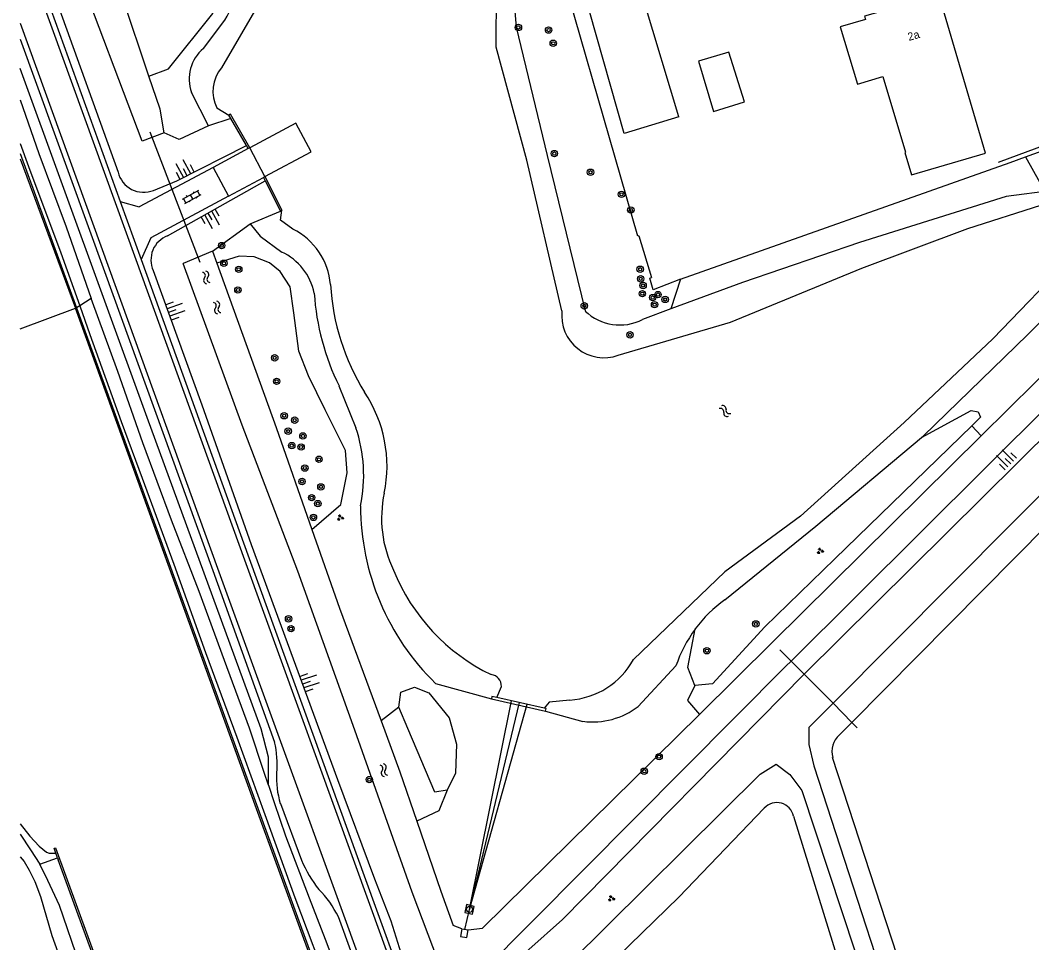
# Model space of a CAD drawing. Extents: x 135999 to 138000, y 396000 to 398501.
# Drawn here: x 136000 to 136126.4, y 396208.2 to 396323.5 of the extents above; entities that cross this region are included whole.
import ezdxf

# ---------------------------------------------------------------- set-up
doc = ezdxf.new("R2010")
doc.units = 0
for name, color, linetype in [('gg-afsc-draadraster', 7, 'Continuous'), ('gg-afsc-erfafscheiding', 7, 'Continuous'), ('gg-afsc-hekwerk', 7, 'Continuous'), ('gg-afsc-muur', 7, 'Continuous'), ('gg-anno-huisnummerreeks BGT', 7, 'Continuous'), ('gg-bbg-bijgebouw', 7, 'Continuous'), ('gg-bbg-gedigitaliseerde bijgebouw', 7, 'Continuous'), ('gg-bbg-hoofdgebouw', 7, 'Continuous'), ('gg-knt-BGT kruinlijn', 7, 'Continuous'), ('gg-knt-bovenkant onderkant talud', 7, 'Continuous'), ('gg-knt-verharding', 7, 'Continuous'), ('gg-knt-verharding nz', 7, 'Continuous'), ('gg-kntw-bovenkant insteek waterloop', 7, 'Continuous'), ('gg-kntw-waterlijn', 7, 'Continuous'), ('gg-kwrk-betonelement', 7, 'Continuous'), ('gg-kwrk-duiker nz buis', 7, 'Continuous'), ('gg-kwrk-keermuur', 7, 'Continuous'), ('gg-kwrk-steiger', 7, 'Continuous'), ('gt-grn-groengrens', 7, 'Continuous'), ('gt-grn-vlakafsluiter', 7, 'Continuous'), ('gt-symb-boom', 7, 'Continuous'), ('gt-symb-groenvak', 7, 'Continuous'), ('gt-symb-klinker verharding', 7, 'Continuous'), ('gt-symb-rioolschacht', 7, 'Continuous'), ('gt-symb-talud symbool', 7, 'Continuous'), ('gt-symb-watersymbool', 7, 'Continuous'), ('gx-grn-maaiveld', 7, 'Continuous')]:
    doc.layers.add(name, color=color, linetype=linetype)

# ---------------------------------------------------------------- blocks, each defined once
blk = doc.blocks.new('gt0-BOOM')
at = {"layer": 'gt-symb-boom'}
for radius in [0.4, 0.2]:
    blk.add_circle((0, 0), radius, dxfattribs=at)
blk = doc.blocks.new('gt0-GRVAK')
at = {"layer": 'gt-symb-groenvak'}
for p, q in [((-0.11, 0.19), (-0.23, 0.24)), ((-0.18, 0.15), (0.09, 0.15)), ((-0.09, 0.21), (-0.16, 0.32)), ((-0.05, 0.21), (-0.05, 0.39)), ((0, 0.21), (0.06, 0.32)), ((0.02, 0.19), (0.13, 0.24)), ((0.26, -0.05), (0.2, 0.06)), ((0.3, -0.05), (0.3, 0.13)), ((0.35, -0.05), (0.41, 0.06)), ((-0.24, -0.23), (-0.36, -0.18)), ((-0.32, -0.26), (-0.05, -0.26)), ((-0.23, -0.21), (-0.29, -0.1)), ((-0.18, -0.2), (-0.18, -0.02)), ((-0.14, -0.21), (-0.07, -0.1)), ((-0.12, -0.23), (0, -0.18)), ((0.24, -0.07), (0.12, -0.02)), ((0.17, -0.11), (0.44, -0.11)), ((0.37, -0.07), (0.49, -0.02))]:
    blk.add_line(p, q, dxfattribs=at)
blk = doc.blocks.new('gt0-TALUD_1')
at = {"layer": 'gt-symb-talud symbool'}
for p, q in [((-1, -1), (-1, 0)), ((-0.5, -2), (-0.5, 0)), ((0, -1), (0, 0)), ((0.5, -2), (0.5, 0)), ((1, -1), (1, 0))]:
    blk.add_line(p, q, dxfattribs=at)
blk = doc.blocks.new('gt0-WA')
at = {"layer": 'gt-symb-watersymbool'}
for centre, start, end in [((-0.32, 0.02), 28.0725, 151.9275), ((0.43, 0.42), 208.0725, 331.9275), ((-0.32, -0.43), 28.0725, 151.9275), ((0.43, -0.03), 208.0725, 331.9275)]:
    blk.add_arc(centre, 0.425, start, end, dxfattribs=at)
blk = doc.blocks.new('gt0-KL1')
at = {"layer": 'gt-symb-klinker verharding'}
for p, q in [((-1.15, 0.3), (1.15, 0.3)), ((-1, -0.3), (-1, 0.3)), ((-0.5, 0.3), (-0.5, 0.45)), ((0, -0.3), (0, 0.3)), ((0.5, 0.3), (0.5, 0.45)), ((1, -0.3), (1, 0.3)), ((-1.15, -0.3), (1.15, -0.3)), ((-0.5, -0.45), (-0.5, -0.3)), ((0.5, -0.45), (0.5, -0.3))]:
    blk.add_line(p, q, dxfattribs=at)
blk = doc.blocks.new('gt0-RS')
at = {"layer": 'gt-symb-rioolschacht'}
blk.add_lwpolyline([(-0.5, -0.5), (0.5, -0.5), (0.5, 0.5), (-0.5, 0.5)], close=True, dxfattribs=at)
blk.add_circle((0, 0), 0.375, dxfattribs=at)

msp = doc.modelspace()

# ---------------------------------------------------------------- linework, layer by layer
at = {"layer": 'gg-afsc-draadraster'}
for points in [[(136125.62, 396306.42), (136139.39, 396311.41), (136159.16, 396318.61)], [(136082.52, 396291.13), (136123.7, 396305.72), (136125.62, 396306.42)]]:
    msp.add_lwpolyline(points, dxfattribs=at)
at = {"layer": 'gg-afsc-erfafscheiding'}
msp.add_line((136077.31, 396296.55), (136078.88, 396291.36), dxfattribs=at)
at = {"layer": 'gg-afsc-hekwerk'}
for p, q in [((136096.32, 396243.39), (136094.91, 396244.81)), ((136097.96, 396241.74), (136096.32, 396243.39)), ((136097.96, 396241.74), (136096.32, 396243.39)), ((136097.96, 396241.74), (136101.56, 396238.11)), ((136097.96, 396241.74), (136101.56, 396238.11)), ((136101.56, 396238.11), (136103.9, 396235.72)), ((136103.9, 396235.72), (136104.56, 396235.04))]:
    msp.add_line(p, q, dxfattribs=at)
msp.add_lwpolyline([(136164.75, 396321.37), (136140.07, 396312.37), (136122.18, 396305.73)], dxfattribs=at)
at = {"layer": 'gg-afsc-muur'}
for p, q in [((136058.88, 396238.66), (136065.64, 396237.12)), ((136065.46, 396237.51), (136059.55, 396238.85))]:
    msp.add_line(p, q, dxfattribs=at)
for points in [[(136059.55, 396238.85), (136058.94, 396238.98), (136058.88, 396238.66)], [(136065.64, 396237.12), (136065.72, 396237.46), (136065.46, 396237.51)]]:
    msp.add_lwpolyline(points, dxfattribs=at)
at = {"layer": 'gg-bbg-bijgebouw'}
for points in [[(136082.31, 396311.42), (136075.46, 396309.35), (136071.18, 396324.49), (136077.76, 396326.53)], [(136088.54, 396319.52), (136084.74, 396318.39), (136086.62, 396312.1), (136090.49, 396313.31), (136088.54, 396319.52)]]:
    msp.add_lwpolyline(points, dxfattribs=at)
at = {"layer": 'gg-bbg-gedigitaliseerde bijgebouw'}
msp.add_line((136082.31, 396311.42), (136078.02, 396325.69), dxfattribs=at)
at = {"layer": 'gg-bbg-hoofdgebouw'}
msp.add_lwpolyline([(136120.61, 396306.9), (136114.88, 396326.48), (136115.66, 396326.71), (136115.6, 396326.91), (136105.5, 396324.01), (136105.62, 396323.62), (136102.46, 396322.67), (136104.61, 396315.52), (136107.77, 396316.48), (136110.62, 396307.01), (136110.53, 396306.98), (136111.37, 396304.19), (136120.61, 396306.9)], dxfattribs=at)
at = {"layer": 'gg-knt-BGT kruinlijn'}
for p, q in [((136000, 396338.48), (136012.22, 396304.51)), ((136018.41, 396296.55), (136030.6, 396303.42))]:
    msp.add_line(p, q, dxfattribs=at)
for points in [[(136097.96, 396241.74), (136142.57, 396285.95), (136173.07, 396316.22)], [(136016.66, 396302.23), (136019.58, 396303.43), (136028.26, 396307.87)], [(136016.63, 396292.22), (136022.7, 396275.44), (136028.87, 396257.96), (136039.65, 396228.6), (136044.28, 396216.18), (136046.32, 396210.91), (136047.56, 396206.9), (136051.38, 396196.06), (136052.81, 396192.4), (136054.26, 396188.42), (136055.79, 396184.75), (136058.58, 396177.23), (136060.05, 396173.56), (136062.86, 396166.3), (136065.69, 396158.09), (136067.16, 396153.6), (136070.41, 396145.41), (136071.87, 396141.49), (136073.34, 396137.14), (136076.44, 396128.34), (136078.07, 396123.94), (136079.51, 396119.81), (136081.08, 396115.98)], [(136099.46, 396076.07), (136105, 396078.09), (136102.59, 396086), (136099.23, 396095.19), (136095.44, 396104.87), (136091.87, 396114.62), (136076.98, 396156.28), (136065.07, 396188.86), (136062.02, 396197.29), (136059.35, 396203.57), (136067.77, 396211.09), (136097.96, 396241.74)]]:
    msp.add_lwpolyline(points, dxfattribs=at)
for centre, radius, start, end in [((136015.43, 396305.31), 3.31, 193.9968, 291.6714), ((136019.53, 396293.56), 3.2, 110.4769, 204.7988)]:
    msp.add_arc(centre, radius, start, end, dxfattribs=at)
at = {"layer": 'gg-knt-bovenkant onderkant talud'}
msp.add_line((136024.02, 396294.62), (136028.75, 396298.07), dxfattribs=at)
msp.add_lwpolyline([(136023.52, 396310.3), (136019.86, 396308.62), (136017.99, 396309.42)], dxfattribs=at)
at = {"layer": 'gg-knt-verharding'}
for p, q in [((136000, 396335.42), (136012.5, 396300.86)), ((136024.09, 396305.09), (136014.85, 396300.19)), ((136026.01, 396301.52), (136016.33, 396296.3)), ((136012.5, 396300.86), (136014.85, 396300.19)), ((136012.5, 396300.86), (136015.12, 396293.6)), ((136016.33, 396296.3), (136015.12, 396293.6)), ((136032.51, 396225.59), (136035.15, 396218.49))]:
    msp.add_line(p, q, dxfattribs=at)
for points in [[(136000, 396321.15), (136010.54, 396292.08), (136024.05, 396254.73), (136031.77, 396233.27)], [(136015.12, 396293.6), (136028.61, 396256.23), (136044.37, 396212.74), (136063.6, 396159.74), (136083.9, 396103.87), (136103.1, 396050.64)], [(136105.83, 396025.3), (136105.27, 396030.32), (136079.38, 396102.18), (136059.08, 396158.12), (136039.75, 396211.42)]]:
    msp.add_lwpolyline(points, dxfattribs=at)
for centre, radius, start, end in [((136020.78, 396230.56), 11.33, 354.1582, 13.8613), ((136042.92, 396228.78), 10.9, 176.6973, 197.0355), ((136047.85, 396223.57), 13.67, 201.8032, 219.6565), ((136027.63, 396205.39), 13.54, 26.4368, 44.2996)]:
    msp.add_arc(centre, radius, start, end, dxfattribs=at)
at = {"layer": 'gg-knt-verharding nz'}
for points in [[(136000, 396333.52), (136014.43, 396293.61), (136028.03, 396256.03), (136043.81, 396212.53), (136062.99, 396159.62), (136083.31, 396103.68), (136102.82, 396049.91), (136105.57, 396041.82), (136108.64, 396032.55), (136110.53, 396027.02)], [(136000, 396323.15), (136011.1, 396292.41), (136024.65, 396254.99), (136040.38, 396211.67), (136059.7, 396158.37), (136079.98, 396102.51), (136107.33, 396025.85)]]:
    msp.add_lwpolyline(points, dxfattribs=at)
at = {"layer": 'gg-kntw-bovenkant insteek waterloop'}
for p, q in [((136016.08, 396316.53), (136011.83, 396329.17)), ((136022.89, 396319.96), (136025.56, 396323.51)), ((136023.52, 396310.3), (136021.4, 396314.49)), ((136026.33, 396311.21), (136023.52, 396310.3)), ((136028.75, 396298.07), (136032.51, 396299.66)), ((136024.02, 396294.62), (136020.35, 396293.09)), ((136024.02, 396294.62), (136024.56, 396293.14)), ((136081.3, 396287.41), (136077.77, 396286.1)), ((136039.83, 396277.79), (136041.95, 396272.56)), ((136077.23, 396237.72), (136081.93, 396242.78)), ((136051.89, 396240.6), (136058.88, 396238.66)), ((136084.86, 396236.72), (136057.77, 396210)), ((136065.64, 396237.12), (136070.32, 396235.85)), ((136055.17, 396209.91), (136054.1, 396210.35)), ((136055.96, 396209.78), (136057.77, 396210))]:
    msp.add_line(p, q, dxfattribs=at)
for points in [[(136101.56, 396238.11), (136146.21, 396283.02), (136182.31, 396318.53), (136148.6, 396349.34)], [(136061.06, 396334.58), (136061.41, 396329.14), (136061.96, 396322.65), (136065.84, 396306.58), (136070.58, 396287.16)], [(136017.99, 396309.42), (136015.23, 396308.4), (136006.93, 396330.37)], [(136017.99, 396309.42), (136017.48, 396312.38), (136016.08, 396316.53)], [(136169.95, 396316.56), (136161.19, 396307.92), (136096.32, 396243.39)], [(136158.3, 396309.14), (136156.82, 396307.63), (136136.93, 396288.21), (136120.09, 396271.55)], [(136129, 396302.22), (136123.21, 396301.49), (136104.89, 396295.72), (136090.26, 396290.74), (136081.3, 396287.41)], [(136028.75, 396298.07), (136030, 396296.52), (136032.68, 396294.53)], [(136024.56, 396293.14), (136031.98, 396272.6), (136036.45, 396259.84)], [(136112.62, 396271.35), (136112.87, 396271.56), (136125.85, 396284.17), (136135.21, 396293.4)], [(136120.09, 396271.55), (136094, 396245.74), (136084.86, 396236.72)], [(136088.05, 396251.06), (136099.42, 396260.26), (136112.62, 396271.35)], [(136036.45, 396259.84), (136039.89, 396250), (136045.1, 396235.92)], [(136057.74, 396204.54), (136095.67, 396242.74), (136096.32, 396243.39)], [(136101.56, 396238.11), (136098.54, 396235.1), (136098.56, 396232.96), (136099.16, 396230.29), (136112.79, 396188.38), (136115.59, 396186.31), (136116.55, 396181.41), (136115.85, 396179.95), (136116.19, 396177.8), (136128.35, 396140.26), (136129.09, 396138.62)], [(136045.1, 396235.92), (136047.45, 396229.56), (136049.56, 396223.38)], [(136066.94, 396202.94), (136068.69, 396205.65), (136092.44, 396229.25), (136094.46, 396230.51), (136096.16, 396229.22), (136097.65, 396227.2), (136110.94, 396187.01), (136110.25, 396184.13), (136111.21, 396181.02), (136113.38, 396179.03), (136114.56, 396176.49), (136127.07, 396137.57), (136128.08, 396134.08)], [(136049.56, 396223.38), (136052.56, 396214.64), (136054.1, 396210.35)]]:
    msp.add_lwpolyline(points, dxfattribs=at)
for centre, radius, start, end in [((136017.07, 396328.8), 10, 328.0603, 19.6418), ((136026, 396316.18), 4.9, 129.421, 200.2034), ((136029.64, 396287.97), 7.23, 11.2888, 65.1731), ((136067.5, 396291.39), 30.83, 183.7293, 206.1772), ((136074.92, 396291.68), 6.27, 226.1784, 297.0462), ((136024.32, 396266.62), 18.6, 348.1374, 18.6065), ((136073.63, 396262.85), 31.11, 180.0953, 225.6687), ((136097.98, 396237.34), 16.94, 125.8733, 143.5668), ((136098, 396237.3), 16.98, 143.5211, 161.1749), ((136071.54, 396245.05), 9.27, 262.4398, 307.8275)]:
    msp.add_arc(centre, radius, start, end, dxfattribs=at)
at = {"layer": 'gg-kntw-waterlijn'}
for p, q in [((136029.85, 396325.66), (136025.15, 396317.56)), ((136024.58, 396312.55), (136026.07, 396311.66)), ((136059.55, 396238.85), (136060.12, 396240.2)), ((136102.33, 396234.14), (136103.9, 396235.72))]:
    msp.add_line(p, q, dxfattribs=at)
for points in [[(136067.69, 396287.18), (136063.31, 396306.01), (136059.47, 396320.13), (136059.5, 396327.2)], [(136103.9, 396235.72), (136144.68, 396276.92), (136184.94, 396317.17)], [(136034.06, 396297.38), (136032.54, 396298.51), (136032.68, 396299.76)], [(136074.72, 396281.64), (136088.75, 396285.76), (136105.15, 396292.53), (136118.42, 396297.48), (136127.55, 396300.39)], [(136131.73, 396294.25), (136121.55, 396283.68), (136110.46, 396273.23), (136097.51, 396261.5), (136088.04, 396254.54), (136076.63, 396243.58)], [(136068.69, 396238.52), (136066.1, 396238.27), (136065.46, 396237.51)], [(136130.86, 396142.59), (136121.77, 396169.2), (136118.71, 396180.62), (136118.51, 396183.1), (136117.85, 396186.47), (136114.96, 396190.11), (136101.51, 396231.33)], [(136071.57, 396203.42), (136082.31, 396213.89), (136092.97, 396225)], [(136096.61, 396223.99), (136102.89, 396203.8), (136108.79, 396186.31), (136108.45, 396183.47), (136109.65, 396179.18), (136111.63, 396177.16), (136121.09, 396149.03), (136125.3, 396135.2)]]:
    msp.add_lwpolyline(points, dxfattribs=at)
for centre, radius, start, end in [((136028.55, 396314.63), 4.48, 139.2819, 207.6533), ((136030.28, 396289.75), 8.52, 4.7681, 63.6968), ((136067.51, 396292.14), 28.79, 183.3553, 211.7191), ((136072.92, 396286.58), 5.26, 173.3909, 290.0668), ((136029.29, 396267.77), 16.54, 348.2242, 33.8987), ((136059.95, 396261.26), 14.8, 167.7527, 206.0154), ((136069.64, 396263.99), 24.77, 201.8599, 244.159), ((136068.06, 396248.26), 9.76, 273.6671, 331.3705), ((136058.7, 396240.28), 1.42, 356.8912, 84.1848), ((136104.11, 396232.1), 2.7, 131.0463, 196.4051), ((136094.54, 396223.59), 2.11, 10.9855, 137.8084)]:
    msp.add_arc(centre, radius, start, end, dxfattribs=at)
at = {"layer": 'gg-kwrk-betonelement'}
msp.add_line((136055.17, 396209.91), (136055.96, 396209.78), dxfattribs=at)
msp.add_lwpolyline([(136055.17, 396209.91), (136055.01, 396208.94), (136055.8, 396208.81), (136055.96, 396209.78)], dxfattribs=at)
at = {"layer": 'gg-kwrk-duiker nz buis'}
for p, q in [((136016.18, 396309.56), (136022.45, 396293.27)), ((136056.14, 396212.34), (136061.4, 396238.43)), ((136062.36, 396238.21), (136056.14, 396212.34)), ((136056.14, 396212.34), (136063.35, 396237.99)), ((136055.56, 396209.85), (136056.14, 396212.34))]:
    msp.add_line(p, q, dxfattribs=at)
at = {"layer": 'gg-kwrk-keermuur'}
for p, q in [((136026.33, 396311.21), (136026.07, 396311.66)), ((136028.26, 396307.87), (136026.33, 396311.21)), ((136028.5, 396307.46), (136028.26, 396307.87)), ((136030.58, 396303.97), (136028.68, 396307.56)), ((136030.38, 396303.86), (136030.6, 396303.42)), ((136030.58, 396303.97), (136032.68, 396299.76)), ((136030.6, 396303.42), (136032.51, 396299.66)), ((136032.68, 396299.76), (136032.51, 396299.66))]:
    msp.add_line(p, q, dxfattribs=at)
msp.add_lwpolyline([(136028.68, 396307.56), (136026.27, 396311.76), (136026.07, 396311.66)], dxfattribs=at)
at = {"layer": 'gg-kwrk-steiger'}
for p, q in [((136028.5, 396307.46), (136024.09, 396305.09)), ((136028.68, 396307.56), (136028.5, 396307.46)), ((136024.09, 396305.09), (136026.01, 396301.52)), ((136026.01, 396301.52), (136030.38, 396303.86)), ((136030.38, 396303.86), (136030.58, 396303.97))]:
    msp.add_line(p, q, dxfattribs=at)
msp.add_lwpolyline([(136030.58, 396303.97), (136036.34, 396307.05), (136034.43, 396310.64), (136028.68, 396307.56)], dxfattribs=at)
at = {"layer": 'gt-grn-groengrens'}
for p, q in [((136082.52, 396291.13), (136081.3, 396287.41)), ((136120.09, 396271.55), (136118.91, 396272.82)), ((136047.3, 396237.64), (136045.1, 396235.92))]:
    msp.add_line(p, q, dxfattribs=at)
for points in [[(136016.08, 396316.53), (136018.53, 396317.44), (136024.06, 396324.36), (136024.76, 396327.29), (136024.76, 396329.69), (136023.89, 396332.12), (136021.53, 396334.66), (136014.43, 396339.36), (136011.15, 396340.74), (136009.46, 396340.21)], [(136125.62, 396306.42), (136127.4, 396303.22), (136129.49, 396302.46)], [(136036.45, 396259.84), (136040.06, 396262.97), (136040.87, 396266.93), (136040.65, 396269.7), (136038.12, 396274.81), (136036.03, 396279.04), (136034.83, 396282.14), (136034.17, 396286.93), (136033.72, 396290.17), (136032.49, 396292.11), (136031.15, 396293.2), (136029.24, 396293.94), (136027.35, 396294.03), (136024.56, 396293.14)], [(136112.62, 396271.35), (136118.82, 396274.72), (136119.68, 396274.57), (136120.01, 396273.89), (136118.91, 396272.82)], [(136118.91, 396272.82), (136101.8, 396256.19), (136093.05, 396247.67), (136086.49, 396240.53), (136084.3, 396240.32)], [(136084.3, 396240.32), (136083.44, 396242.58), (136084.35, 396247.4)], [(136047.3, 396237.64), (136047.56, 396239.5), (136049.26, 396240.13), (136051.04, 396239.43), (136053.61, 396236.3), (136054.51, 396233), (136054.37, 396229.38), (136053.33, 396227.23)], [(136084.3, 396240.32), (136083.38, 396238.48), (136084.86, 396236.72)], [(136053.33, 396227.23), (136051.8, 396227.02), (136048.43, 396234.98), (136047.3, 396237.64)], [(136053.33, 396227.23), (136052.29, 396224.65), (136049.56, 396223.38)]]:
    msp.add_lwpolyline(points, dxfattribs=at)
at = {"layer": 'gt-grn-vlakafsluiter'}
for points in [[(136077.31, 396296.55), (136077.16, 396296.53), (136065.05, 396338.63)], [(136082.52, 396291.13), (136079.1, 396289.79), (136078.68, 396291.25), (136078.88, 396291.36)]]:
    msp.add_lwpolyline(points, dxfattribs=at)
at = {"layer": 'gx-grn-maaiveld'}
for p, q in [((136000, 396306.85), (136007.05, 396287.55)), ((136000, 396306.18), (136006.91, 396287.5)), ((136008.86, 396288.71), (136007.43, 396287.79)), ((136000, 396284.94), (136006.91, 396287.5)), ((136007.05, 396287.55), (136006.91, 396287.5)), ((136007.43, 396287.79), (136007.05, 396287.55)), ((136004.66, 396218.8), (136004.44, 396219.39)), ((136002.43, 396217.98), (136004.66, 396218.8)), ((136004.66, 396218.8), (136004.76, 396218.53))]:
    msp.add_line(p, q, dxfattribs=at)
for points in [[(136031.01, 396227.87), (136031.03, 396231.37), (136030.09, 396234.9), (136015.85, 396273.86), (136000, 396317.46)], [(136000, 396313.54), (136002.32, 396306.84), (136005.73, 396297.68), (136008.86, 396288.71)], [(136000, 396308.12), (136001.05, 396305.22), (136005.09, 396294.41), (136007.43, 396287.79)], [(136053.57, 396202.39), (136048.97, 396214.5), (136041.82, 396234.74), (136034.69, 396254.61), (136027.74, 396272.89), (136020.35, 396293.09)], [(136031.01, 396227.87), (136030.5, 396229.47), (136028.66, 396235.01), (136025.52, 396243.47), (136022.36, 396252.08), (136018.92, 396261.02), (136015.32, 396270.69), (136012.21, 396279.58), (136008.86, 396288.71)], [(136094.99, 396044.94), (136082.59, 396079), (136059.03, 396143.91), (136029.52, 396224.93), (136006.91, 396287.5)], [(136007.05, 396287.55), (136029.67, 396224.98), (136059.17, 396143.96), (136082.73, 396079.05), (136095.15, 396044.98)], [(136007.43, 396287.79), (136008.69, 396284.2), (136012.6, 396273.36), (136015.24, 396266.24), (136019.2, 396255.52), (136023.15, 396244.45), (136027.05, 396233.89), (136030.55, 396224.19), (136034.32, 396213.85), (136037.41, 396205.66)], [(136031.01, 396227.87), (136031.71, 396225.71), (136033.14, 396221.53), (136036.12, 396213.8), (136038.09, 396208.61), (136041.36, 396200.03), (136044.72, 396190.61), (136048.1, 396181.06), (136057.74, 396154.22), (136065, 396134.72), (136076.3, 396103.81), (136087.04, 396074.62)], [(136000, 396223.05), (136001.21, 396221.51), (136002.37, 396220.24), (136003.27, 396219.5), (136003.61, 396219.37), (136004.44, 396219.39)], [(136000, 396221.75), (136001.29, 396219.81), (136002.43, 396217.98)], [(136000, 396218.93), (136000.48, 396218.35), (136001.12, 396217.26), (136001.81, 396215.81), (136002.52, 396213.95), (136003.93, 396209.09), (136005.07, 396205.95), (136006.79, 396201.36), (136009.22, 396194.78), (136011.61, 396188.86)], [(136004.44, 396219.39), (136004.22, 396219.99), (136004.39, 396220.05), (136018.14, 396182.33), (136017.97, 396182.27), (136017.65, 396183.15)], [(136015.15, 396182.28), (136015.12, 396182.51), (136015.02, 396183.85), (136014.89, 396185.08), (136014.64, 396186.11), (136012.92, 396190.57), (136009.79, 396198.47), (136008.17, 396202.83), (136007.8, 396204.14), (136007.44, 396205.41), (136004.92, 396212.84), (136003.45, 396215.97), (136002.43, 396217.98)], [(136017.41, 396183.82), (136012.69, 396196.76), (136007.08, 396212.13), (136004.76, 396218.53)]]:
    msp.add_lwpolyline(points, dxfattribs=at)

# ---------------------------------------------------------------- block references
at = {"layer": 'gt-symb-boom'}
for p in [(136062.25, 396322.61), (136066.02, 396322.28), (136066.6, 396320.63), (136066.74, 396306.84), (136071.26, 396304.51), (136075.13, 396301.75), (136076.3, 396299.78), (136025.17, 396295.34), (136025.45, 396293.13), (136027.31, 396292.37), (136077.46, 396292.38), (136077.53, 396291.18), (136027.2, 396289.78), (136077.74, 396289.32), (136077.83, 396290.35), (136079.02, 396288.84), (136079.26, 396287.95), (136079.69, 396289.21), (136080.59, 396288.6), (136070.48, 396287.8), (136076.2, 396284.18), (136031.8, 396281.3), (136032.04, 396278.37), (136032.98, 396274.06), (136034.3, 396273.51), (136033.48, 396272.13), (136035.32, 396271.54), (136033.93, 396270.33), (136035.1, 396270.16), (136037.33, 396268.62), (136035.56, 396267.52), (136035.21, 396265.84), (136037.57, 396265.17), (136036.42, 396263.82), (136037.19, 396263.08), (136036.64, 396261.35), (136033.53, 396248.67), (136091.92, 396248.04), (136033.84, 396247.44), (136085.8, 396244.68), (136079.83, 396231.44), (136043.62, 396228.57), (136077.97, 396229.62)]:
    msp.add_blockref('gt0-BOOM', p, dxfattribs=at)
at = {"layer": 'gt-symb-groenvak'}
for p in [(136039.99, 396261.31), (136099.95, 396257.15), (136073.85, 396213.71)]:
    msp.add_blockref('gt0-GRVAK', p, dxfattribs=at)
at = {"layer": 'gt-symb-klinker verharding', "rotation": 28.998977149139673}
msp.add_blockref('gt0-KL1', (136021.44, 396301.43), dxfattribs=at)
at = {"layer": 'gt-symb-rioolschacht', "rotation": 167.75305577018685}
msp.add_blockref('gt0-RS', (136056.14, 396212.34), dxfattribs=at)
at = {"layer": 'gt-symb-talud symbool'}
for p, xscale, yscale, rotation in [((136020.83, 396304.1), 0.9996084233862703, 0.9996084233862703, -151.5633713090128), ((136023.5, 396299.41), 0.9996489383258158, 0.9996489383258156, 29.154810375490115), ((136018.52, 396286.97), 1.000466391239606, 1.0004663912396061, 109.68464273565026), ((136123.77, 396268.03), 1.000562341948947, 1.000562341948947, -134.79754225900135), ((136035.28, 396240.51), 1.0005518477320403, 1.0005518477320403, 108.65225162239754)]:
    msp.add_blockref('gt0-TALUD_1', p, dxfattribs=dict(at, xscale=xscale, yscale=yscale, rotation=rotation))
at = {"layer": 'gt-symb-watersymbool'}
for p, rotation in [((136023.22, 396291.41), -70.06095208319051), ((136024.59, 396287.64), -70.06095208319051), ((136088.01, 396274.69), -39.11608916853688), ((136045.41, 396229.8), -70.55043123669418)]:
    msp.add_blockref('gt0-WA', p, dxfattribs=dict(at, rotation=rotation))

# ---------------------------------------------------------------- texts
at = {"layer": 'gg-anno-huisnummerreeks BGT'}
msp.add_text('2a', height=1, rotation=16, dxfattribs=at).set_placement((136111.05, 396320.92))

doc.saveas('drawing.dxf')
